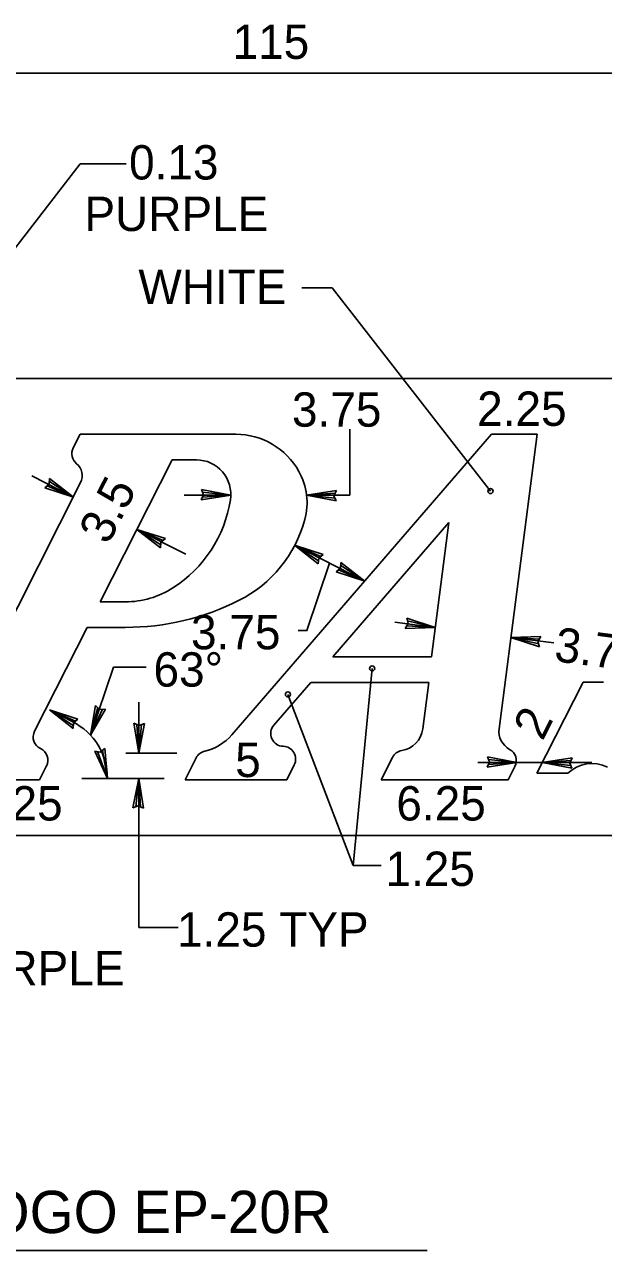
# Model space of a CAD drawing. Extents: x 10268197 to 10268739, y 2141503 to 2142677.
# Drawn here: x 10268700.09 to 10268711.88, y 2142399.34 to 2142424.33 of the extents above; entities that cross this region are included whole.
import ezdxf

# ---------------------------------------------------------------- set-up
doc = ezdxf.new("R2010")
doc.units = 0
for name, color, linetype in [('1', 7, 'Continuous'), ('21', 7, 'Continuous'), ('Default', 7, 'Continuous')]:
    doc.layers.add(name, color=color, linetype=linetype)

msp = doc.modelspace()

# ---------------------------------------------------------------- linework, layer by layer
at = {"layer": '1'}
for p, q in [((10268681.389, 2142423.333), (10268706.542, 2142423.333)), ((10268706.542, 2142423.333), (10268729.003, 2142423.333)), ((10268699.201, 2142418.868), (10268701.226, 2142421.486)), ((10268701.226, 2142421.486), (10268702.162, 2142421.486)), ((10268705.739, 2142418.959), (10268706.355, 2142418.959)), ((10268706.355, 2142418.959), (10268709.583, 2142414.819)), ((10268706.718, 2142414.734), (10268706.718, 2142416.079)), ((10268700.24, 2142415.127), (10268701.086, 2142414.696)), ((10268700.593, 2142414.958), (10268700.503, 2142414.885)), ((10268700.603, 2142415.073), (10268700.593, 2142414.958)), ((10268701.086, 2142414.696), (10268700.598, 2142415.013)), ((10268701.086, 2142414.696), (10268700.603, 2142415.073)), ((10268701.086, 2142414.696), (10268700.503, 2142414.885)), ((10268701.086, 2142414.696), (10268700.551, 2142414.923)), ((10268703.346, 2142414.734), (10268704.297, 2142414.734)), ((10268703.74, 2142414.744), (10268703.691, 2142414.638)), ((10268704.297, 2142414.734), (10268703.691, 2142414.638)), ((10268704.297, 2142414.734), (10268703.695, 2142414.851)), ((10268703.695, 2142414.851), (10268703.74, 2142414.744)), ((10268704.297, 2142414.734), (10268703.717, 2142414.693)), ((10268704.297, 2142414.734), (10268703.719, 2142414.794)), ((10268705.837, 2142414.734), (10268706.443, 2142414.83)), ((10268705.837, 2142414.734), (10268706.417, 2142414.774)), ((10268705.837, 2142414.734), (10268706.718, 2142414.734)), ((10268705.837, 2142414.734), (10268706.439, 2142414.617)), ((10268705.837, 2142414.734), (10268706.416, 2142414.674)), ((10268706.395, 2142414.724), (10268706.443, 2142414.83)), ((10268706.439, 2142414.617), (10268706.395, 2142414.724)), ((10268702.379, 2142414.038), (10268703.376, 2142413.53)), ((10268702.379, 2142414.038), (10268702.962, 2142413.849)), ((10268702.379, 2142414.038), (10268702.862, 2142413.661)), ((10268702.379, 2142414.038), (10268702.867, 2142413.722)), ((10268702.379, 2142414.038), (10268702.914, 2142413.811)), ((10268702.862, 2142413.661), (10268702.871, 2142413.777)), ((10268702.871, 2142413.777), (10268702.962, 2142413.849)), ((10268705.592, 2142413.714), (10268707.02, 2142412.986)), ((10268705.592, 2142413.714), (10268706.175, 2142413.525)), ((10268705.592, 2142413.714), (10268706.076, 2142413.337)), ((10268705.592, 2142413.714), (10268706.081, 2142413.398)), ((10268705.592, 2142413.714), (10268706.127, 2142413.487)), ((10268706.076, 2142413.337), (10268706.085, 2142413.453)), ((10268706.085, 2142413.453), (10268706.175, 2142413.525)), ((10268708.458, 2142412.036), (10268707.876, 2142412.23)), ((10268707.876, 2142412.23), (10268707.906, 2142412.118)), ((10268708.458, 2142412.036), (10268707.636, 2142412.144)), ((10268707.906, 2142412.118), (10268707.845, 2142412.019)), ((10268708.458, 2142412.036), (10268707.845, 2142412.019)), ((10268708.458, 2142412.036), (10268707.877, 2142412.071)), ((10268708.458, 2142412.036), (10268707.892, 2142412.171)), ((10268709.997, 2142411.837), (10268710.61, 2142411.854)), ((10268709.997, 2142411.837), (10268710.875, 2142411.723)), ((10268709.997, 2142411.837), (10268710.579, 2142411.643)), ((10268709.997, 2142411.837), (10268710.564, 2142411.703)), ((10268709.997, 2142411.837), (10268710.577, 2142411.803)), ((10268710.549, 2142411.756), (10268710.61, 2142411.854)), ((10268710.579, 2142411.643), (10268710.549, 2142411.756)), ((10268701.904, 2142411.227), (10268701.435, 2142409.843)), ((10268702.57, 2142411.227), (10268701.904, 2142411.227)), ((10268706.786, 2142407.185), (10268707.173, 2142411.204)), ((10268702.417, 2142409.48), (10268702.417, 2142410.516)), ((10268706.786, 2142407.185), (10268705.458, 2142410.675)), ((10268701.074, 2142410.115), (10268700.598, 2142410.358)), ((10268700.598, 2142410.358), (10268701.18, 2142410.169)), ((10268700.598, 2142410.358), (10268701.08, 2142409.981)), ((10268700.598, 2142410.358), (10268701.085, 2142410.042)), ((10268700.598, 2142410.358), (10268701.132, 2142410.131)), ((10268701.435, 2142409.843), (10268701.538, 2142410.446)), ((10268701.435, 2142409.843), (10268701.583, 2142410.405)), ((10268701.435, 2142409.843), (10268701.738, 2142410.375)), ((10268701.435, 2142409.843), (10268701.678, 2142410.371)), ((10268701.623, 2142410.367), (10268701.538, 2142410.446)), ((10268701.738, 2142410.375), (10268701.623, 2142410.367)), ((10268701.08, 2142409.981), (10268701.09, 2142410.097)), ((10268701.09, 2142410.097), (10268701.18, 2142410.169)), ((10268702.417, 2142409.48), (10268702.321, 2142410.086)), ((10268702.426, 2142410.038), (10268702.321, 2142410.086)), ((10268702.417, 2142409.48), (10268702.376, 2142410.06)), ((10268702.417, 2142409.48), (10268702.534, 2142410.082)), ((10268702.417, 2142409.48), (10268702.477, 2142410.059)), ((10268702.534, 2142410.082), (10268702.426, 2142410.038)), ((10268701.78, 2142408.963), (10268701.521, 2142409.519)), ((10268701.635, 2142409.501), (10268701.521, 2142409.519)), ((10268701.78, 2142408.963), (10268701.581, 2142409.509)), ((10268701.726, 2142409.573), (10268701.635, 2142409.501)), ((10268701.78, 2142408.963), (10268701.679, 2142409.535)), ((10268701.78, 2142408.963), (10268701.726, 2142409.573)), ((10268703.193, 2142409.48), (10268702.158, 2142409.48)), ((10268710.121, 2142409.286), (10268709.325, 2142409.286)), ((10268710.638, 2142409.286), (10268710.121, 2142409.286)), ((10268711.648, 2142409.286), (10268710.638, 2142409.286)), ((10268702.934, 2142408.963), (10268701.262, 2142408.963)), ((10268702.417, 2142408.963), (10268702.3, 2142408.361)), ((10268702.417, 2142408.963), (10268702.356, 2142408.385)), ((10268702.417, 2142408.963), (10268702.417, 2142405.927)), ((10268702.417, 2142408.963), (10268702.513, 2142408.358)), ((10268702.417, 2142408.963), (10268702.457, 2142408.383)), ((10268702.3, 2142408.361), (10268702.407, 2142408.406)), ((10268702.407, 2142408.406), (10268702.513, 2142408.358)), ((10268707.358, 2142407.185), (10268706.786, 2142407.185)), ((10268702.417, 2142405.927), (10268703.224, 2142405.927))]:
    msp.add_line(p, q, dxfattribs=at)
msp.add_lwpolyline([(10268705.668, 2142411.975), (10268705.843, 2142411.975), (10268706.306, 2142413.35)], dxfattribs=at)
for centre in [(10268709.583, 2142414.819), (10268707.173, 2142411.204), (10268705.458, 2142410.675)]:
    msp.add_circle(centre, 0.0518, dxfattribs=at)
msp.add_arc((10268700.486, 2142408.964), 1.294, 0, 62.9941, dxfattribs=at)
at = {"layer": '21'}
for p, q in [((10268706.527, 2142413.248), (10268706.436, 2142413.176)), ((10268707.02, 2142412.986), (10268706.484, 2142413.214)), ((10268706.536, 2142413.364), (10268706.527, 2142413.248)), ((10268707.02, 2142412.986), (10268706.531, 2142413.303)), ((10268707.02, 2142412.986), (10268706.536, 2142413.364)), ((10268707.02, 2142412.986), (10268706.436, 2142413.176)), ((10268709.563, 2142409.296), (10268709.515, 2142409.19)), ((10268710.121, 2142409.286), (10268709.515, 2142409.19)), ((10268710.121, 2142409.286), (10268709.519, 2142409.403)), ((10268709.519, 2142409.403), (10268709.563, 2142409.296)), ((10268710.121, 2142409.286), (10268709.541, 2142409.245)), ((10268710.121, 2142409.286), (10268709.542, 2142409.346)), ((10268710.638, 2142409.286), (10268711.245, 2142409.382)), ((10268710.638, 2142409.286), (10268711.219, 2142409.327)), ((10268710.638, 2142409.286), (10268711.241, 2142409.169)), ((10268710.638, 2142409.286), (10268711.218, 2142409.225)), ((10268711.197, 2142409.276), (10268711.245, 2142409.382)), ((10268711.241, 2142409.169), (10268711.197, 2142409.276)), ((10268697.392, 2142399.342), (10268708.293, 2142399.342))]:
    msp.add_line(p, q, dxfattribs=at)
at = {"layer": 'Default'}
for p, q in [((10268699.479, 2142417.115), (10268729.003, 2142417.115)), ((10268701.225, 2142415.976), (10268701.084, 2142415.698)), ((10268704.395, 2142415.976), (10268701.225, 2142415.976)), ((10268704.315, 2142409.852), (10268709.6, 2142415.976)), ((10268709.6, 2142415.976), (10268710.532, 2142415.976)), ((10268710.532, 2142415.976), (10268709.757, 2142409.976)), ((10268701.632, 2142412.561), (10268703.096, 2142415.455)), ((10268703.096, 2142415.455), (10268703.595, 2142415.455)), ((10268701.234, 2142414.991), (10268698.672, 2142409.923)), ((10268708.734, 2142414.178), (10268706.371, 2142411.44)), ((10268708.38, 2142411.44), (10268708.734, 2142414.178)), ((10268702.144, 2142412.561), (10268701.632, 2142412.561)), ((10268700.298, 2142409.924), (10268701.368, 2142412.04)), ((10268701.368, 2142412.04), (10268702.144, 2142412.04)), ((10268706.371, 2142411.44), (10268708.38, 2142411.44)), ((10268705.923, 2142410.918), (10268705.172, 2142410.049)), ((10268708.328, 2142410.918), (10268705.923, 2142410.918)), ((10268708.205, 2142409.976), (10268708.328, 2142410.918)), ((10268710.528, 2142409.068), (10268711.468, 2142410.926)), ((10268711.468, 2142410.926), (10268711.883, 2142410.926)), ((10268700.397, 2142408.937), (10268700.539, 2142409.216)), ((10268703.363, 2142408.937), (10268703.588, 2142409.383)), ((10268705.586, 2142409.239), (10268705.433, 2142408.937)), ((10268707.357, 2142408.937), (10268707.585, 2142409.389)), ((10268710.081, 2142409.206), (10268709.945, 2142408.937)), ((10268711.157, 2142409.068), (10268710.528, 2142409.068)), ((10268697.81, 2142408.937), (10268700.397, 2142408.937)), ((10268705.433, 2142408.937), (10268703.363, 2142408.937)), ((10268709.945, 2142408.937), (10268707.357, 2142408.937)), ((10268698.615, 2142407.798), (10268724.257, 2142407.798))]:
    msp.add_line(p, q, dxfattribs=at)
for centre, major_axis, start_param, end_param in [((10268704.395, 2142414.49), (0, 1.486), 5.226065, 6.283185), ((10268701.315, 2142415.58), (0, -0.261), 4.240773, 5.605302), ((10268703.594, 2142414.751), (0, -0.704), 1.415043, 3.141593), ((10268700.958, 2142415.133), (0, -0.313), 1.099604, 2.46371), ((10268704.553, 2142414.58), (0, 1.303), 4.445482, 5.226065), ((10268701.728, 2142415.046), (0, -2.607), 0.565847, 1.415043), ((10268703.304, 2142414.924), (0, -2.607), 0.465011, 1.30389), ((10268702.144, 2142414.386), (0, -1.825), 0, 0.565847), ((10268702.144, 2142417.254), (0, -5.214), 0, 0.465011), ((10268705.367, 2142409.878), (0, 0.261), 0.854904, 3.118676), ((10268707.692, 2142410.043), (0, -0.521), 0.161263, 1.440999), ((10268710.168, 2142409.922), (0, 0.417), 1.441439, 2.650585), ((10268700.528, 2142409.806), (0, 0.261), 1.099355, 2.701477), ((10268703.534, 2142410.537), (0, -1.043), 0.22194, 0.855152), ((10268700.308, 2142409.334), (0, 0.261), 4.241567, 5.84307), ((10268703.819, 2142409.265), (0, -0.261), 3.363532, 4.241567), ((10268705.355, 2142409.357), (0, 0.261), 4.240773, 6.260268), ((10268707.816, 2142409.272), (0, -0.261), 3.302856, 4.241567), ((10268709.85, 2142409.324), (0, 0.261), 4.240773, 5.792177), ((10268711.653, 2142408.536), (0, -0.73), 2.69443, 3.895387)]:
    msp.add_ellipse(centre, major_axis=major_axis, ratio=0.992614, start_param=start_param, end_param=end_param, dxfattribs=at)

# ---------------------------------------------------------------- texts
at = {"layer": '1'}
for s, height, p in [('115', 0.7, (10268704.329, 2142423.627)), ('0.13', 0.7, (10268702.221, 2142421.169)), ('PURPLE', 0.7, (10268701.312, 2142420.119)), ('WHITE', 0.7, (10268702.411, 2142418.631)), ('3.75', 0.7, (10268705.539, 2142416.131)), ('2.25', 0.7, (10268709.311, 2142416.148)), ('63°', 0.7, (10268702.719, 2142410.833)), ('5', 0.7, (10268704.383, 2142408.99)), ('6.25', 0.7, (10268699.046, 2142408.105)), ('6.25', 0.7, (10268707.665, 2142408.105)), ('1.25', 0.7, (10268707.443, 2142406.771)), ('1.25 TYP', 0.7, (10268703.198, 2142405.534)), ('PURPLE', 0.7, (10268698.382, 2142404.746)), ('LOGO EP-20R', 0.8624, (10268698.657, 2142399.696))]:
    msp.add_text(s, height=height, dxfattribs=at).set_placement(p)
for s, rotation, p in [('3.5', 62.9907, (10268701.795, 2142413.705)), ('3.75', 360, (10268703.483, 2142411.594)), ('3.75', 352.5994, (10268710.861, 2142411.355)), ('2', 63, (10268710.641, 2142409.708))]:
    msp.add_text(s, height=0.7, rotation=rotation, dxfattribs=at).set_placement(p)

doc.saveas('drawing.dxf')
